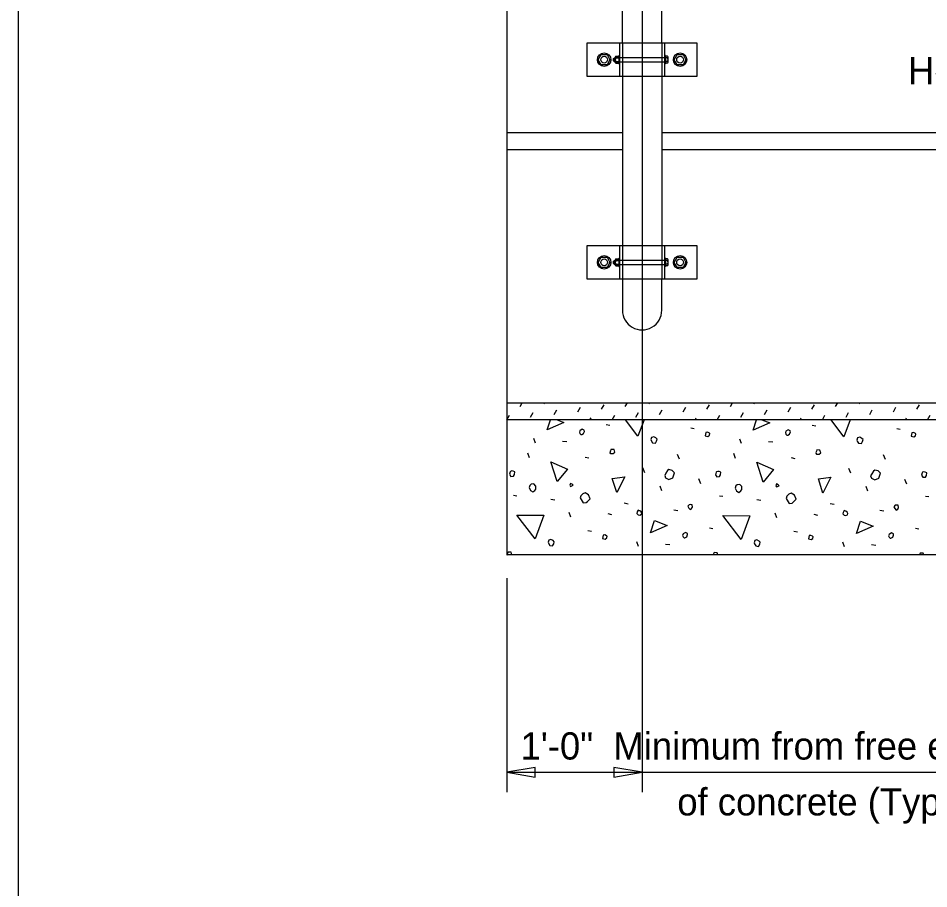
# Model space of a CAD drawing. Extents: x 0 to 72.1, y -15.2 to 30.1.
# Drawn here: x 0.02 to 6.75, y 12.68 to 19.13 of the extents above; entities that cross this region are included whole.
import ezdxf

# ---------------------------------------------------------------- set-up
doc = ezdxf.new("R2010")
doc.units = 0
for name, color, linetype in [('ActivePts-ConstElements', 7, 'Continuous'), ('AdhocPoint_dp', 7, 'Continuous'), ('Border', 7, 'Continuous'), ('Patterning', 7, 'Continuous'), ('PlotBorder_dp', 7, 'Continuous'), ('SheetBorder_dp', 7, 'Continuous'), ('SheetLines_dp', 7, 'Continuous'), ('TextMisc', 7, 'Continuous')]:
    doc.layers.add(name, color=color, linetype=linetype)

msp = doc.modelspace()

# ---------------------------------------------------------------- linework, layer by layer
at = {"layer": 'ActivePts-ConstElements'}
msp.add_lwpolyline([(0.016, 2.0538), (41.0666, 2.0538), (41.0666, 27.9999), (0.016, 27.9999)], close=True, dxfattribs=at)
at = {"layer": 'AdhocPoint_dp'}
for p, q in [((3.6311, 19.2783), (3.6311, 15.1533)), ((3.6311, 18.2783), (4.4852, 18.2783)), ((4.7769, 18.2783), (14.4852, 18.2783)), ((3.6311, 18.1533), (4.4853, 18.1533)), ((4.7769, 18.1533), (14.4853, 18.1533)), ((3.6311, 16.2783), (16.018, 16.2783)), ((16.018, 16.1533), (3.6311, 16.1533)), ((16.018, 15.1533), (3.6311, 15.1533))]:
    msp.add_line(p, q, dxfattribs=at)
at = {"layer": 'Border'}
for p, q in [((4.4852, 18.9432), (4.4852, 18.6932)), ((4.7769, 18.9432), (4.7769, 18.6932)), ((4.7978, 18.8328), (4.4329, 18.8328)), ((4.4329, 18.8029), (4.7978, 18.8029)), ((4.4852, 17.4432), (4.4852, 17.1932)), ((4.7769, 17.4432), (4.7769, 17.1932)), ((4.7978, 17.3328), (4.4329, 17.3328)), ((4.4329, 17.3029), (4.7978, 17.3029))]:
    msp.add_line(p, q, dxfattribs=at)
at = {"layer": 'Patterning'}
for p, q in [((4.4235, 18.8113), (4.4235, 18.8234)), ((4.4292, 18.8113), (4.4292, 18.8234)), ((4.4235, 17.3113), (4.4235, 17.3234)), ((4.4292, 17.3113), (4.4292, 17.3234)), ((3.7283, 16.2506), (3.7444, 16.2783)), ((3.9033, 16.27), (3.9081, 16.2783)), ((4.1561, 16.2117), (4.1755, 16.2453)), ((4.3311, 16.2311), (4.3505, 16.2647)), ((4.5061, 16.2506), (4.5222, 16.2783)), ((4.6811, 16.27), (4.6859, 16.2783)), ((4.9339, 16.2117), (4.9534, 16.2453)), ((5.1089, 16.2311), (5.1284, 16.2647)), ((5.2839, 16.2506), (5.3, 16.2783)), ((5.4589, 16.27), (5.4637, 16.2783)), ((5.7117, 16.2117), (5.7312, 16.2453)), ((5.8867, 16.2311), (5.9062, 16.2647)), ((6.0617, 16.2506), (6.0778, 16.2783)), ((6.2367, 16.27), (6.2416, 16.2783)), ((6.4895, 16.2117), (6.509, 16.2453)), ((6.6645, 16.2311), (6.684, 16.2647)), ((3.6311, 16.1533), (3.6505, 16.1869)), ((3.8061, 16.1728), (3.8255, 16.2064)), ((3.9811, 16.1922), (4.0005, 16.2258)), ((4.2451, 16.1533), (4.2533, 16.1675)), ((4.4089, 16.1533), (4.4283, 16.1869)), ((4.5839, 16.1728), (4.6033, 16.2064)), ((4.7589, 16.1922), (4.7783, 16.2258)), ((5.0229, 16.1533), (5.0311, 16.1675)), ((5.1867, 16.1533), (5.2061, 16.1869)), ((5.3617, 16.1728), (5.3811, 16.2064)), ((5.5367, 16.1922), (5.5562, 16.2258)), ((5.8008, 16.1533), (5.8089, 16.1675)), ((5.9645, 16.1533), (5.984, 16.1869)), ((6.1395, 16.1728), (6.159, 16.2064)), ((6.3145, 16.1922), (6.334, 16.2258)), ((6.5786, 16.1533), (6.5868, 16.1675)), ((6.7423, 16.1533), (6.7618, 16.1869)), ((4.3649, 16.118), (4.3914, 16.1127)), ((5.8887, 16.1144), (5.9152, 16.1091)), ((4.9907, 16.0932), (5.0172, 16.0879)), ((6.5145, 16.0897), (6.541, 16.0844)), ((3.8416, 15.9801), (3.8292, 16.0137)), ((4.0414, 15.996), (4.0732, 15.9925)), ((5.3654, 15.9766), (5.3531, 16.0101)), ((5.5652, 15.9925), (5.597, 15.9889)), ((3.7992, 15.8705), (3.785, 15.9058)), ((4.9076, 15.8617), (4.8934, 15.897)), ((5.323, 15.867), (5.3089, 15.9023)), ((4.2093, 15.8776), (4.2376, 15.8705)), ((5.7331, 15.874), (5.7614, 15.867)), ((6.4314, 15.8581), (6.4173, 15.8935)), ((4.6513, 15.7609), (4.6371, 15.7962)), ((6.1751, 15.7574), (6.1609, 15.7927)), ((5.0649, 15.6796), (5.0508, 15.7149)), ((6.5887, 15.676), (6.5746, 15.7114)), ((4.7768, 15.6283), (4.7644, 15.6619)), ((6.3006, 15.6248), (6.2882, 15.6584)), ((3.679, 15.5947), (3.7037, 15.5912)), ((3.9548, 15.5664), (3.9848, 15.5611)), ((5.2028, 15.5912), (5.2275, 15.5877)), ((5.4786, 15.5629), (5.5086, 15.5576)), ((6.7266, 15.5877), (6.7514, 15.5841)), ((4.4992, 15.5382), (4.5275, 15.5311)), ((6.023, 15.5346), (6.0513, 15.5275)), ((4.1032, 15.4321), (4.0909, 15.4657)), ((4.3772, 15.4586), (4.4055, 15.4515)), ((4.8652, 15.4869), (4.8952, 15.4816)), ((5.6271, 15.4286), (5.6147, 15.4621)), ((5.9011, 15.4551), (5.9293, 15.448)), ((6.389, 15.4834), (6.419, 15.478)), ((3.6311, 15.3526), (3.6313, 15.3525)), ((4.2305, 15.3331), (4.257, 15.3278)), ((5.1286, 15.3543), (5.1551, 15.349)), ((5.7543, 15.3296), (5.7809, 15.3243)), ((6.6524, 15.3508), (6.6789, 15.3455)), ((4.6053, 15.2164), (4.5929, 15.25)), ((4.805, 15.2323), (4.8369, 15.2288)), ((6.1291, 15.2129), (6.1167, 15.2465)), ((6.3289, 15.2288), (6.3607, 15.2253))]:
    msp.add_line(p, q, dxfattribs=at)
for points in [[(3.93, 16.0791), (3.9528, 16.1533)], [(4.0029, 16.1533), (4.052, 16.1339), (3.93, 16.0791)], [(4.6, 16.0314), (4.5073, 16.1533)], [(4.6456, 16.1533), (4.6, 16.0314)], [(5.4538, 16.0756), (5.4778, 16.1533)], [(5.5178, 16.1533), (5.5758, 16.1304), (5.4538, 16.0756)], [(6.1238, 16.0278), (6.0284, 16.1533)], [(6.1707, 16.1533), (6.1238, 16.0278)], [(4.1775, 16.0437), (4.1846, 16.0437), (4.1987, 16.0508), (4.204, 16.0667), (4.2022, 16.0756), (4.1881, 16.0826), (4.1704, 16.072), (4.1669, 16.0614), (4.1704, 16.0508), (4.1775, 16.0437)], [(5.0985, 16.0349), (5.1179, 16.0296), (5.1303, 16.0384), (5.1321, 16.0508), (5.1286, 16.0543), (5.1144, 16.0614), (5.102, 16.0596), (5.1003, 16.0473), (5.0985, 16.0349)], [(5.7013, 16.0402), (5.7084, 16.0402), (5.7225, 16.0473), (5.7278, 16.0632), (5.7261, 16.072), (5.7119, 16.0791), (5.6942, 16.0685), (5.6907, 16.0579), (5.6942, 16.0473), (5.7013, 16.0402)], [(6.6223, 16.0314), (6.6418, 16.0261), (6.6541, 16.0349), (6.6559, 16.0473), (6.6524, 16.0508), (6.6382, 16.0579), (6.6258, 16.0561), (6.6241, 16.0437), (6.6223, 16.0314)], [(4.699, 15.9995), (4.7078, 15.9836), (4.729, 15.9801), (4.7379, 15.996), (4.7414, 16.0101), (4.7326, 16.019), (4.7167, 16.0278), (4.7008, 16.0225), (4.6954, 16.0066), (4.699, 15.9995)], [(6.2228, 15.996), (6.2316, 15.9801), (6.2529, 15.9766), (6.2617, 15.9925), (6.2652, 16.0066), (6.2564, 16.0155), (6.2405, 16.0243), (6.2246, 16.019), (6.2193, 16.0031), (6.2228, 15.996)], [(4.3967, 15.9023), (4.4179, 15.9023), (4.4285, 15.9129), (4.4232, 15.9324), (4.4002, 15.9341), (4.3967, 15.9235), (4.3914, 15.9147), (4.3967, 15.9023), (4.3932, 15.9058)], [(5.9205, 15.8988), (5.9417, 15.8988), (5.9523, 15.9094), (5.947, 15.9288), (5.924, 15.9306), (5.9205, 15.92), (5.9152, 15.9112), (5.9205, 15.8988), (5.917, 15.9023)], [(4.0025, 15.6955), (3.9548, 15.8422), (4.0803, 15.7874), (4.0025, 15.6955)], [(5.5263, 15.6919), (5.4786, 15.8387), (5.6041, 15.7839), (5.5263, 15.6919)], [(3.6507, 15.7503), (3.6595, 15.7344), (3.679, 15.7361), (3.6878, 15.7485), (3.6896, 15.768), (3.6772, 15.7733), (3.6684, 15.775), (3.6578, 15.7715), (3.6542, 15.768), (3.6507, 15.7503)], [(4.805, 15.7238), (4.828, 15.7114), (4.8581, 15.7238), (4.8705, 15.7609), (4.8528, 15.7786), (4.8298, 15.7839), (4.8192, 15.7768), (4.8068, 15.7574), (4.798, 15.7414), (4.805, 15.7238)], [(5.1745, 15.7468), (5.1834, 15.7308), (5.2028, 15.7326), (5.2116, 15.745), (5.2134, 15.7644), (5.201, 15.7697), (5.1922, 15.7715), (5.1816, 15.768), (5.178, 15.7644), (5.1745, 15.7468)], [(6.3289, 15.7202), (6.3518, 15.7079), (6.3819, 15.7202), (6.3943, 15.7574), (6.3766, 15.775), (6.3536, 15.7803), (6.343, 15.7733), (6.3306, 15.7538), (6.3218, 15.7379), (6.3289, 15.7202)], [(6.6983, 15.7432), (6.7072, 15.7273), (6.7266, 15.7291), (6.7355, 15.7414), (6.7372, 15.7609), (6.7248, 15.7662), (6.716, 15.768), (6.7054, 15.7644), (6.7019, 15.7609), (6.6983, 15.7432)], [(4.4444, 15.6142), (4.4108, 15.7185), (4.5045, 15.7308), (4.4444, 15.6142)], [(5.9682, 15.6106), (5.9347, 15.7149), (6.0283, 15.7273), (5.9682, 15.6106)], [(3.7957, 15.6513), (3.8063, 15.6301), (3.8239, 15.6195), (3.8381, 15.6301), (3.8452, 15.6407), (3.8452, 15.6619), (3.8292, 15.6778), (3.8098, 15.676), (3.801, 15.6672), (3.7957, 15.6513)], [(4.1015, 15.6601), (4.1209, 15.669), (4.1139, 15.676), (4.1015, 15.6813), (4.0962, 15.669), (4.1015, 15.6601)], [(5.3195, 15.6478), (5.3301, 15.6265), (5.3478, 15.6159), (5.3619, 15.6265), (5.369, 15.6371), (5.369, 15.6584), (5.3531, 15.6743), (5.3336, 15.6725), (5.3248, 15.6637), (5.3195, 15.6478)], [(5.6253, 15.6566), (5.6447, 15.6654), (5.6377, 15.6725), (5.6253, 15.6778), (5.62, 15.6654), (5.6253, 15.6566)], [(4.1722, 15.5753), (4.1952, 15.5382), (4.2182, 15.5399), (4.227, 15.5488), (4.2464, 15.5682), (4.2341, 15.5983), (4.2093, 15.6124), (4.1916, 15.6053), (4.1775, 15.5912), (4.1722, 15.5753)], [(5.696, 15.5717), (5.719, 15.5346), (5.742, 15.5364), (5.7508, 15.5452), (5.7703, 15.5647), (5.7579, 15.5947), (5.7331, 15.6089), (5.7154, 15.6018), (5.7013, 15.5877), (5.696, 15.5717)], [(4.9765, 15.4993), (4.9871, 15.4887), (4.9977, 15.4957), (5.0048, 15.5063), (5.0013, 15.524), (4.9924, 15.5258), (4.9801, 15.524), (4.9695, 15.5134), (4.9765, 15.4993)], [(6.5003, 15.4957), (6.5109, 15.4851), (6.5216, 15.4922), (6.5286, 15.5028), (6.5251, 15.5205), (6.5162, 15.5222), (6.5039, 15.5205), (6.4933, 15.5099), (6.5003, 15.4957)], [(3.8398, 15.2712), (3.7055, 15.448), (3.9053, 15.4462), (3.8398, 15.2712)], [(4.6018, 15.4498), (4.6141, 15.448), (4.6265, 15.4533), (4.63, 15.4639), (4.6247, 15.4727), (4.6141, 15.4798), (4.6018, 15.4851), (4.5947, 15.471), (4.5911, 15.4604), (4.6018, 15.4498)], [(5.3637, 15.2677), (5.2293, 15.4445), (5.4291, 15.4427), (5.3637, 15.2677)], [(6.1256, 15.4462), (6.1379, 15.4445), (6.1503, 15.4498), (6.1539, 15.4604), (6.1486, 15.4692), (6.1379, 15.4763), (6.1256, 15.4816), (6.1185, 15.4674), (6.115, 15.4568), (6.1256, 15.4462)], [(4.6937, 15.3154), (4.722, 15.4073), (4.8157, 15.3702), (4.6937, 15.3154)], [(6.2175, 15.3119), (6.2458, 15.4038), (6.3395, 15.3667), (6.2175, 15.3119)], [(4.3384, 15.2748), (4.3578, 15.2695), (4.3702, 15.2783), (4.3719, 15.2907), (4.3684, 15.2942), (4.3543, 15.3013), (4.3419, 15.2995), (4.3401, 15.2871), (4.3384, 15.2748)], [(4.9412, 15.2801), (4.9482, 15.2801), (4.9624, 15.2871), (4.9677, 15.303), (4.9659, 15.3119), (4.9518, 15.319), (4.9341, 15.3083), (4.9306, 15.2977), (4.9341, 15.2871), (4.9412, 15.2801)], [(5.8622, 15.2712), (5.8816, 15.2659), (5.894, 15.2748), (5.8958, 15.2871), (5.8922, 15.2907), (5.8781, 15.2977), (5.8657, 15.296), (5.8639, 15.2836), (5.8622, 15.2712)], [(6.465, 15.2765), (6.4721, 15.2765), (6.4862, 15.2836), (6.4915, 15.2995), (6.4897, 15.3083), (6.4756, 15.3154), (6.4579, 15.3048), (6.4544, 15.2942), (6.4579, 15.2836), (6.465, 15.2765)], [(3.9388, 15.2394), (3.9477, 15.2235), (3.9689, 15.22), (3.9777, 15.2359), (3.9813, 15.25), (3.9724, 15.2588), (3.9565, 15.2677), (3.9406, 15.2624), (3.9353, 15.2465), (3.9388, 15.2394)], [(5.4627, 15.2359), (5.4715, 15.22), (5.4927, 15.2164), (5.5015, 15.2323), (5.5051, 15.2465), (5.4962, 15.2553), (5.4803, 15.2642), (5.4644, 15.2588), (5.4591, 15.2429), (5.4627, 15.2359)], [(3.6682, 15.1533), (3.6631, 15.1722), (3.6401, 15.174), (3.6366, 15.1634), (3.6313, 15.1545), (3.6318, 15.1533)], [(5.1911, 15.1533), (5.1869, 15.1687), (5.1639, 15.1705), (5.1604, 15.1599), (5.1565, 15.1533)], [(6.7139, 15.1533), (6.7107, 15.1652), (6.6877, 15.1669), (6.6842, 15.1563), (6.6824, 15.1533)]]:
    msp.add_lwpolyline(points, dxfattribs=at)
at = {"layer": 'PlotBorder_dp'}
for p, q in [((3.6311, 14.9799), (3.6311, 13.3959)), ((3.6311, 13.5439), (8.4056, 13.5439))]:
    msp.add_line(p, q, dxfattribs=at)
for points in [[(3.6311, 13.544), (3.8393, 13.5087), (3.8393, 13.5792)], [(4.6311, 13.544), (4.4228, 13.5793), (4.4228, 13.5087)]]:
    msp.add_lwpolyline(points, close=True, dxfattribs=at)
at = {"layer": 'SheetBorder_dp'}
msp.add_line((4.631, 27.6465), (4.631, 13.3959), dxfattribs=at)
at = {"layer": 'TextMisc'}
for p, q in [((4.4852, 18.9432), (4.4852, 19.4191)), ((4.7769, 18.9432), (4.7769, 19.4191)), ((4.2251, 18.9432), (5.0371, 18.9432)), ((4.2251, 18.6932), (4.2251, 18.9432)), ((4.4644, 18.9432), (4.4644, 18.6932)), ((4.7977, 18.9432), (4.7977, 18.6932)), ((5.0371, 18.9432), (5.0371, 18.6932)), ((4.4207, 18.8262), (4.4263, 18.8328)), ((4.4207, 18.8085), (4.4207, 18.8262)), ((4.4207, 18.8085), (4.4263, 18.8029)), ((4.4263, 18.8328), (4.4329, 18.8328)), ((4.4263, 18.8029), (4.4263, 18.8328)), ((4.4263, 18.8029), (4.4329, 18.8029)), ((4.4329, 18.8361), (4.4329, 18.8004)), ((4.4376, 18.8312), (4.4579, 18.8312)), ((4.4376, 18.8053), (4.4579, 18.8053)), ((4.4378, 18.8442), (4.4579, 18.8442)), ((4.4579, 18.8485), (4.4579, 18.7879)), ((4.4579, 18.8485), (4.4644, 18.8485)), ((4.4579, 18.8442), (4.4579, 18.7922)), ((4.804, 18.8485), (4.798, 18.8485)), ((4.804, 18.8485), (4.804, 18.7879)), ((4.8187, 18.8442), (4.804, 18.8442)), ((4.8189, 18.8312), (4.804, 18.8312)), ((4.8189, 18.8052), (4.804, 18.8052)), ((4.8238, 18.7988), (4.8238, 18.8377)), ((4.4379, 18.7922), (4.4579, 18.7922)), ((4.4579, 18.7879), (4.4644, 18.7879)), ((4.804, 18.7879), (4.798, 18.7879)), ((4.8187, 18.7922), (4.804, 18.7922)), ((5.0371, 18.6932), (4.2251, 18.6932)), ((4.4852, 18.6932), (4.4852, 17.4432)), ((4.7769, 18.6932), (4.7769, 17.4432)), ((4.2251, 17.4432), (5.0371, 17.4432)), ((4.2251, 17.1932), (4.2251, 17.4432)), ((4.4644, 17.4432), (4.4644, 17.1932)), ((4.7977, 17.4432), (4.7977, 17.1932)), ((5.0371, 17.4432), (5.0371, 17.1932)), ((4.4207, 17.3262), (4.4263, 17.3328)), ((4.4207, 17.3085), (4.4207, 17.3262)), ((4.4263, 17.3328), (4.4329, 17.3328)), ((4.4263, 17.3029), (4.4263, 17.3328)), ((4.4329, 17.3361), (4.4329, 17.3004)), ((4.4376, 17.3312), (4.4579, 17.3312)), ((4.4378, 17.3442), (4.4579, 17.3442)), ((4.4579, 17.3485), (4.4579, 17.2879)), ((4.4579, 17.3485), (4.4644, 17.3485)), ((4.4579, 17.3442), (4.4579, 17.2922)), ((4.804, 17.3485), (4.798, 17.3485)), ((4.804, 17.3485), (4.804, 17.2879)), ((4.8187, 17.3442), (4.804, 17.3442)), ((4.8189, 17.3312), (4.804, 17.3312)), ((4.8238, 17.2988), (4.8238, 17.3377)), ((4.4207, 17.3085), (4.4263, 17.3029)), ((4.4263, 17.3029), (4.4329, 17.3029)), ((4.4376, 17.3053), (4.4579, 17.3053)), ((4.4379, 17.2922), (4.4579, 17.2922)), ((4.4579, 17.2879), (4.4644, 17.2879)), ((4.804, 17.2879), (4.798, 17.2879)), ((4.8189, 17.3052), (4.804, 17.3052)), ((4.8187, 17.2922), (4.804, 17.2922)), ((5.0371, 17.1932), (4.2251, 17.1932)), ((4.4851, 17.1932), (4.4851, 16.964)), ((4.7768, 16.964), (4.7768, 17.1932))]:
    msp.add_line(p, q, dxfattribs=at)
for points in [[(4.3284, 18.8557), (4.3718, 18.8557), (4.3934, 18.8182), (4.3718, 18.7807), (4.3284, 18.7807), (4.3067, 18.8182)], [(4.8904, 18.8557), (4.9337, 18.8557), (4.9554, 18.8182), (4.9337, 18.7807), (4.8904, 18.7807), (4.8687, 18.8182)], [(4.3284, 17.3557), (4.3718, 17.3557), (4.3934, 17.3182), (4.3718, 17.2807), (4.3284, 17.2807), (4.3067, 17.3182)], [(4.8904, 17.3557), (4.9337, 17.3557), (4.9554, 17.3182), (4.9337, 17.2807), (4.8904, 17.2807), (4.8687, 17.3182)]]:
    msp.add_lwpolyline(points, close=True, dxfattribs=at)
for centre, radius in [((4.3501, 18.8182), 0.05), ((4.9121, 18.8182), 0.05), ((4.3501, 18.8182), 0.025), ((4.9121, 18.8182), 0.025), ((4.3501, 17.3182), 0.05), ((4.3501, 17.3182), 0.025), ((4.9121, 17.3182), 0.05), ((4.9121, 17.3182), 0.025)]:
    msp.add_circle(centre, radius, dxfattribs=at)
for centre, radius, start, end in [((4.4394, 18.8377), 0.00674, 104.48908, 254.18889), ((4.4523, 18.8182), 0.0196, 138.62797, 221.37203), ((4.4394, 18.7987), 0.00673, 105.7823, 255.54039), ((4.817, 18.8376), 0.00673, 285.7823, 75.54039), ((4.817, 18.7987), 0.00674, 284.48908, 74.18889), ((4.8041, 18.8182), 0.0196, 318.62797, 41.37203), ((4.4394, 17.3377), 0.00674, 104.48908, 254.18889), ((4.4523, 17.3182), 0.0196, 138.62797, 221.37203), ((4.817, 17.3376), 0.00673, 285.7823, 75.54039), ((4.8041, 17.3182), 0.0196, 318.62797, 41.37203), ((4.4394, 17.2987), 0.00673, 105.7823, 255.54039), ((4.817, 17.2987), 0.00674, 284.48908, 74.18889)]:
    msp.add_arc(centre, radius, start, end, dxfattribs=at)
msp.add_ellipse((4.631, 16.964), major_axis=(0, 0.1458), ratio=0.999499, start_param=1.570796, end_param=4.712389, dxfattribs=at)

# ---------------------------------------------------------------- texts
at = {"layer": 'SheetLines_dp'}
for s, p in [('Hog Rings @ 2\'-0" Centers', (6.5976, 18.6361)), ('1\'-0"  Minimum from free end ', (3.7321, 13.6383)), ('of concrete (Typ.)', (4.8914, 13.2248))]:
    msp.add_text(s, height=0.2016, dxfattribs=at).set_placement(p)

doc.saveas('drawing.dxf')
